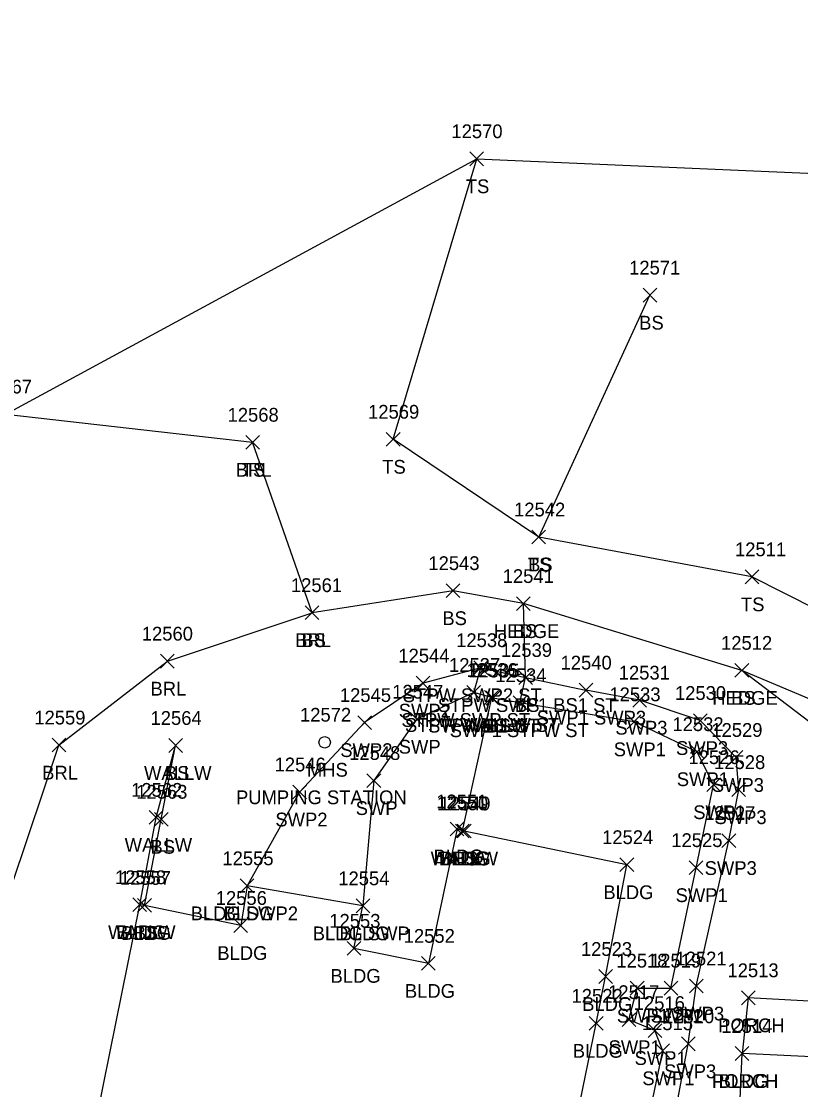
# Model space of a CAD drawing. Extents: x 1482574 to 1485769, y 580696 to 595649.
# Drawn here: x 1482734.1 to 1482847.5, y 584017.2 to 584172.5 of the extents above; entities that cross this region are included whole.
import ezdxf

# ---------------------------------------------------------------- set-up
doc = ezdxf.new("R2010")
doc.units = 0
for name, color, linetype in [('L_A', 7, 'Continuous'), ('L_I', 7, 'Continuous'), ('L_TIC', 7, 'Continuous'), ('LABL', 7, 'Continuous'), ('LAHR', 7, 'Continuous'), ('LBC', 7, 'Continuous'), ('LBF', 7, 'Continuous'), ('LELB', 7, 'Continuous'), ('LSOGP', 7, 'Continuous'), ('LW', 7, 'Continuous'), ('R_A', 7, 'Continuous'), ('R_I', 7, 'Continuous'), ('R_TIC', 7, 'Continuous'), ('RSW', 7, 'Continuous'), ('U_A', 7, 'Continuous'), ('U_C', 7, 'Continuous'), ('U_I', 7, 'Continuous'), ('USMH', 7, 'Continuous')]:
    doc.layers.add(name, color=color, linetype=linetype)

msp = doc.modelspace()

# ---------------------------------------------------------------- linework, layer by layer
at = {"layer": 'L_TIC'}
for points in [[(1482799.36, 584151.56), (1482801.36, 584153.56)], [(1482801.36, 584151.56), (1482799.36, 584153.56)], [(1482824.54, 584131.73), (1482826.54, 584133.73)], [(1482826.54, 584131.73), (1482824.54, 584133.73)], [(1482766.77, 584110.34), (1482768.77, 584112.34)], [(1482768.77, 584110.34), (1482766.77, 584112.34)], [(1482766.77, 584110.34), (1482768.77, 584112.34)], [(1482768.77, 584110.34), (1482766.77, 584112.34)], [(1482787.21, 584110.78), (1482789.21, 584112.78)], [(1482789.21, 584110.78), (1482787.21, 584112.78)], [(1482808.38, 584096.57), (1482810.38, 584098.57)], [(1482810.38, 584096.57), (1482808.38, 584098.57)], [(1482808.38, 584096.57), (1482810.38, 584098.57)], [(1482810.38, 584096.57), (1482808.38, 584098.57)], [(1482839.37, 584090.78), (1482841.37, 584092.78)], [(1482841.37, 584090.78), (1482839.37, 584092.78)], [(1482795.92, 584088.77), (1482797.92, 584090.77)], [(1482797.92, 584088.77), (1482795.92, 584090.77)], [(1482806.15, 584086.89), (1482808.15, 584088.89)], [(1482808.15, 584086.89), (1482806.15, 584088.89)], [(1482806.15, 584086.89), (1482808.15, 584088.89)], [(1482808.15, 584086.89), (1482806.15, 584088.89)], [(1482775.41, 584085.57), (1482777.41, 584087.57)], [(1482777.41, 584085.57), (1482775.41, 584087.57)], [(1482775.41, 584085.57), (1482777.41, 584087.57)], [(1482777.41, 584085.57), (1482775.41, 584087.57)], [(1482754.38, 584078.52), (1482756.38, 584080.52)], [(1482756.38, 584078.52), (1482754.38, 584080.52)], [(1482799.96, 584077.57), (1482801.96, 584079.57)], [(1482801.96, 584077.57), (1482799.96, 584079.57)], [(1482837.91, 584077.18), (1482839.91, 584079.18)], [(1482839.91, 584077.18), (1482837.91, 584079.18)], [(1482837.91, 584077.18), (1482839.91, 584079.18)], [(1482839.91, 584077.18), (1482837.91, 584079.18)], [(1482806.47, 584076.14), (1482808.47, 584078.14)], [(1482808.47, 584076.14), (1482806.47, 584078.14)], [(1482806.47, 584076.14), (1482808.47, 584078.14)], [(1482808.47, 584076.14), (1482806.47, 584078.14)], [(1482798.92, 584073.97), (1482800.92, 584075.97)], [(1482800.92, 584073.97), (1482798.92, 584075.97)], [(1482801.51, 584073.24), (1482803.51, 584075.24)], [(1482803.51, 584073.24), (1482801.51, 584075.24)], [(1482801.51, 584073.24), (1482803.51, 584075.24)], [(1482803.51, 584073.24), (1482801.51, 584075.24)], [(1482801.72, 584073.15), (1482803.72, 584075.15)], [(1482803.72, 584073.15), (1482801.72, 584075.15)], [(1482801.72, 584073.15), (1482803.72, 584075.15)], [(1482803.72, 584073.15), (1482801.72, 584075.15)], [(1482805.65, 584072.48), (1482807.65, 584074.48)], [(1482807.65, 584072.48), (1482805.65, 584074.48)], [(1482738.62, 584066.32), (1482740.62, 584068.32)], [(1482740.62, 584066.32), (1482738.62, 584068.32)], [(1482755.57, 584066.26), (1482757.57, 584068.26)], [(1482757.57, 584066.26), (1482755.57, 584068.26)], [(1482755.57, 584066.26), (1482757.57, 584068.26)], [(1482757.57, 584066.26), (1482755.57, 584068.26)], [(1482752.75, 584055.81), (1482754.75, 584057.81)], [(1482754.75, 584055.81), (1482752.75, 584057.81)], [(1482753.49, 584055.53), (1482755.49, 584057.53)], [(1482755.49, 584055.53), (1482753.49, 584057.53)], [(1482796.5, 584054.13), (1482798.5, 584056.13)], [(1482798.5, 584054.13), (1482796.5, 584056.13)], [(1482797.25, 584053.85), (1482799.25, 584055.85)], [(1482799.25, 584053.85), (1482797.25, 584055.85)], [(1482797.25, 584053.85), (1482799.25, 584055.85)], [(1482799.25, 584053.85), (1482797.25, 584055.85)], [(1482797.53, 584053.83), (1482799.53, 584055.83)], [(1482799.53, 584053.83), (1482797.53, 584055.83)], [(1482797.53, 584053.83), (1482799.53, 584055.83)], [(1482799.53, 584053.83), (1482797.53, 584055.83)], [(1482821.18, 584048.93), (1482823.18, 584050.93)], [(1482823.18, 584048.93), (1482821.18, 584050.93)], [(1482765.97, 584045.86), (1482767.97, 584047.86)], [(1482767.97, 584045.86), (1482765.97, 584047.86)], [(1482750.35, 584043.11), (1482752.35, 584045.11)], [(1482752.35, 584043.11), (1482750.35, 584045.11)], [(1482750.35, 584043.11), (1482752.35, 584045.11)], [(1482752.35, 584043.11), (1482750.35, 584045.11)], [(1482750.35, 584043.11), (1482752.35, 584045.11)], [(1482752.35, 584043.11), (1482750.35, 584045.11)], [(1482751.05, 584043.01), (1482753.05, 584045.01)], [(1482753.05, 584043.01), (1482751.05, 584045.01)], [(1482751.05, 584043.01), (1482753.05, 584045.01)], [(1482753.05, 584043.01), (1482751.05, 584045.01)], [(1482782.82, 584042.95), (1482784.82, 584044.95)], [(1482784.82, 584042.95), (1482782.82, 584044.95)], [(1482765.05, 584040.09), (1482767.05, 584042.09)], [(1482767.05, 584040.09), (1482765.05, 584042.09)], [(1482781.51, 584036.77), (1482783.51, 584038.77)], [(1482783.51, 584036.77), (1482781.51, 584038.77)], [(1482792.33, 584034.58), (1482794.33, 584036.58)], [(1482794.33, 584034.58), (1482792.33, 584036.58)], [(1482818.1, 584032.68), (1482820.1, 584034.68)], [(1482820.1, 584032.68), (1482818.1, 584034.68)], [(1482838.85, 584029.58), (1482840.85, 584031.58)], [(1482840.85, 584029.58), (1482838.85, 584031.58)], [(1482816.73, 584025.87), (1482818.73, 584027.87)], [(1482818.73, 584025.87), (1482816.73, 584027.87)], [(1482837.94, 584021.48), (1482839.94, 584023.48)], [(1482839.94, 584021.48), (1482837.94, 584023.48)], [(1482837.94, 584021.48), (1482839.94, 584023.48)], [(1482839.94, 584021.48), (1482837.94, 584023.48)], [(1482837.94, 584021.48), (1482839.94, 584023.48)], [(1482839.94, 584021.48), (1482837.94, 584023.48)]]:
    msp.add_lwpolyline(points, dxfattribs=at)
at = {"layer": 'LABL'}
msp.add_lwpolyline([(1482753.56, 583847.65), (1482763.33, 583886.22), (1482745, 583925.11), (1482720.19, 583937.3), (1482697, 583950.74), (1482684.74, 583977.37), (1482717.6, 583981.37), (1482723.72, 584020.13), (1482739.62, 584067.32), (1482755.38, 584079.52), (1482776.41, 584086.57), (1482767.77, 584111.34)], dxfattribs=at)
at = {"layer": 'LAHR'}
msp.add_lwpolyline([(1482928.6, 584026.89), (1482913.75, 584044.71), (1482891.08, 584056.23), (1482855.52, 584065.51), (1482838.91, 584078.18), (1482807.15, 584087.89)], dxfattribs=at)
at = {"layer": 'LBC'}
for points in [[(1482808.73, 583982.89), (1482817.73, 584026.87), (1482819.1, 584033.68), (1482822.18, 584049.93), (1482798.53, 584054.83), (1482798.25, 584054.85), (1482797.5, 584055.13), (1482793.33, 584035.58), (1482782.51, 584037.77), (1482783.82, 584043.95), (1482766.97, 584046.86), (1482766.05, 584041.09), (1482752.05, 584044.01), (1482751.35, 584044.11)], [(1482741.74, 583996.43), (1482751.35, 584044.11)], [(1482837.55, 583990.35), (1482890.4, 583987.41), (1482892.38, 583987.48), (1482894.08, 584019.69), (1482891.62, 584019.98), (1482838.94, 584022.48)], [(1482837.55, 583990.35), (1482838.94, 584022.48)]]:
    msp.add_lwpolyline(points, dxfattribs=at)
at = {"layer": 'LBF'}
for points in [[(1482806.65, 584073.48), (1482802.72, 584074.15), (1482802.51, 584074.24), (1482799.92, 584074.97), (1482800.96, 584078.57), (1482807.47, 584077.14)], [(1482891.62, 584019.98), (1482892.34, 584027.71), (1482839.85, 584030.58), (1482838.94, 584022.48)]]:
    msp.add_lwpolyline(points, dxfattribs=at)
at = {"layer": 'LELB'}
for points in [[(1482942.03, 583859.02), (1482934.27, 583897.38), (1482938.31, 583954.48), (1482940.22, 584002.41), (1482937.55, 584028.27), (1482922.03, 584053.68), (1482893.04, 584067.31), (1482864.04, 584079.81), (1482840.37, 584091.78), (1482809.38, 584097.57), (1482788.21, 584111.78), (1482800.36, 584152.56)], [(1482809.38, 584097.57), (1482825.54, 584132.73)], [(1482704.84, 584111.05), (1482731.9, 584115.44), (1482767.77, 584111.34)], [(1482807.47, 584077.14), (1482807.15, 584087.89), (1482796.92, 584089.77), (1482776.41, 584086.57)], [(1482935.97, 583858.21), (1482928.85, 583898.87), (1482930.75, 583906.84), (1482932.59, 583955.77), (1482933.96, 584002.2), (1482933.04, 584027.34), (1482916.05, 584047.49), (1482891.95, 584059.4), (1482858.9, 584069.72), (1482838.91, 584078.18)], [(1482752.05, 584044.01), (1482754.49, 584056.53), (1482756.57, 584067.26)]]:
    msp.add_lwpolyline(points, dxfattribs=at)
at = {"layer": 'LSOGP'}
msp.add_lwpolyline([(1482624.36, 583828.83), (1482673.16, 583862.27), (1482696.29, 583884.43), (1482694.49, 583917.75), (1482678.31, 583954.25), (1482684.74, 583977.37), (1482695.23, 584028.52), (1482699.57, 584054.68), (1482704.09, 584083.33), (1482704.84, 584111.05), (1482731.9, 584115.44), (1482800.36, 584152.56), (1482886.43, 584148.82), (1482927.74, 584160.45), (1482970.01, 584172.54)], dxfattribs=at)
at = {"layer": 'LW'}
for points in [[(1482802.51, 584074.24), (1482798.25, 584054.85)], [(1482751.35, 584044.11), (1482753.75, 584056.81), (1482756.57, 584067.26)]]:
    msp.add_lwpolyline(points, dxfattribs=at)
at = {"layer": 'R_TIC'}
for points in [[(1482799.96, 584077.57), (1482801.96, 584079.57)], [(1482801.96, 584077.57), (1482799.96, 584079.57)], [(1482791.55, 584075.33), (1482793.55, 584077.33)], [(1482793.55, 584075.33), (1482791.55, 584077.33)], [(1482806.47, 584076.14), (1482808.47, 584078.14)], [(1482808.47, 584076.14), (1482806.47, 584078.14)], [(1482798.92, 584073.97), (1482800.92, 584075.97)], [(1482800.92, 584073.97), (1482798.92, 584075.97)], [(1482815.23, 584074.31), (1482817.23, 584076.31)], [(1482817.23, 584074.31), (1482815.23, 584076.31)], [(1482815.23, 584074.31), (1482817.23, 584076.31)], [(1482817.23, 584074.31), (1482815.23, 584076.31)], [(1482805.65, 584072.48), (1482807.65, 584074.48)], [(1482807.65, 584072.48), (1482805.65, 584074.48)], [(1482823.04, 584072.85), (1482825.04, 584074.85)], [(1482825.04, 584072.85), (1482823.04, 584074.85)], [(1482783.05, 584069.59), (1482785.05, 584071.59)], [(1482785.05, 584069.59), (1482783.05, 584071.59)], [(1482790.66, 584070.08), (1482792.66, 584072.08)], [(1482792.66, 584070.08), (1482790.66, 584072.08)], [(1482822.24, 584069.7), (1482824.24, 584071.7)], [(1482824.24, 584069.7), (1482822.24, 584071.7)], [(1482831.86, 584069.89), (1482833.86, 584071.89)], [(1482833.86, 584069.89), (1482831.86, 584071.89)], [(1482831.41, 584065.36), (1482833.41, 584067.36)], [(1482833.41, 584065.36), (1482831.41, 584067.36)], [(1482837.07, 584064.52), (1482839.07, 584066.52)], [(1482839.07, 584064.52), (1482837.07, 584066.52)], [(1482784.4, 584061.16), (1482786.4, 584063.16)], [(1482786.4, 584061.16), (1482784.4, 584063.16)], [(1482833.8, 584060.56), (1482835.8, 584062.56)], [(1482835.8, 584060.56), (1482833.8, 584062.56)], [(1482837.46, 584059.84), (1482839.46, 584061.84)], [(1482839.46, 584059.84), (1482837.46, 584061.84)], [(1482773.61, 584059.5), (1482775.61, 584061.5)], [(1482775.61, 584059.5), (1482773.61, 584061.5)], [(1482836.02, 584052.44), (1482838.02, 584054.44)], [(1482838.02, 584052.44), (1482836.02, 584054.44)], [(1482831.25, 584048.5), (1482833.25, 584050.5)], [(1482833.25, 584048.5), (1482831.25, 584050.5)], [(1482765.97, 584045.86), (1482767.97, 584047.86)], [(1482767.97, 584045.86), (1482765.97, 584047.86)], [(1482782.82, 584042.95), (1482784.82, 584044.95)], [(1482784.82, 584042.95), (1482782.82, 584044.95)], [(1482822.69, 584030.98), (1482824.69, 584032.98)], [(1482824.69, 584030.98), (1482822.69, 584032.98)], [(1482827.59, 584030.98), (1482829.59, 584032.98)], [(1482829.59, 584030.98), (1482827.59, 584032.98)], [(1482831.28, 584031.29), (1482833.28, 584033.29)], [(1482833.28, 584031.29), (1482831.28, 584033.29)], [(1482821.49, 584026.4), (1482823.49, 584028.4)], [(1482823.49, 584026.4), (1482821.49, 584028.4)], [(1482825.27, 584024.82), (1482827.27, 584026.82)], [(1482827.27, 584024.82), (1482825.27, 584026.82)], [(1482830.12, 584022.89), (1482832.12, 584024.89)], [(1482832.12, 584022.89), (1482830.12, 584024.89)], [(1482826.4, 584021.88), (1482828.4, 584023.88)], [(1482828.4, 584021.88), (1482826.4, 584023.88)]]:
    msp.add_lwpolyline(points, dxfattribs=at)
at = {"layer": 'RSW'}
for points in [[(1482800.96, 584078.57), (1482792.55, 584076.33), (1482784.05, 584070.59), (1482774.61, 584060.5), (1482766.97, 584046.86)], [(1482823.31, 583939.7), (1482822.04, 583959.32), (1482819.45, 583984.29), (1482821.45, 583994.26), (1482827.4, 584022.88), (1482826.27, 584025.82), (1482822.49, 584027.4), (1482823.69, 584031.98), (1482828.59, 584031.98), (1482832.25, 584049.5), (1482834.8, 584061.56), (1482832.41, 584066.36), (1482823.24, 584070.7), (1482806.65, 584073.48), (1482807.47, 584077.14), (1482816.23, 584075.31)], [(1482799.92, 584074.97), (1482791.66, 584071.08), (1482785.4, 584062.16), (1482783.82, 584043.95)], [(1482827.72, 583940.25), (1482825.42, 583959.17), (1482823.58, 583984.19), (1482827.5, 583986.02), (1482836.38, 583984.37), (1482836.5, 583988.78), (1482826.87, 583989.35), (1482825.22, 583992.27), (1482831.12, 584023.89), (1482832.28, 584032.29), (1482837.02, 584053.44), (1482838.46, 584060.84), (1482838.07, 584065.52), (1482832.86, 584070.89), (1482824.04, 584073.85), (1482816.23, 584075.31)]]:
    msp.add_lwpolyline(points, dxfattribs=at)
at = {"layer": 'USMH'}
for p, q in [((1482778.25, 584067.73), (1482778.25, 584067.73)), ((1482779.08, 584067.73), (1482779.08, 584067.73))]:
    msp.add_line(p, q, dxfattribs=at)
msp.add_circle((1482778.25, 584067.73), 0.833, dxfattribs=at)

# ---------------------------------------------------------------- texts
at = {"layer": 'L_A'}
for s, p in [('TS', (1482798.77, 584147.56)), ('BS', (1482823.98, 584127.73)), ('BRL', (1482765.31, 584106.34)), ('TS', (1482766.18, 584106.34)), ('TS', (1482786.62, 584106.78)), ('TS', (1482807.79, 584092.57)), ('BS', (1482807.82, 584092.57)), ('TS', (1482838.78, 584086.78)), ('BS', (1482795.36, 584084.77)), ('HEDGE', (1482802.85, 584082.89)), ('BS', (1482805.59, 584082.89)), ('BRL', (1482773.96, 584081.57)), ('BS', (1482774.86, 584081.57)), ('BRL', (1482752.92, 584074.52)), ('STPW SWP2 ST', (1482789.6, 584073.57)), ('STPW SWP1 BS1 ST', (1482794.69, 584072.14)), ('BS', (1482805.91, 584072.14)), ('HEDGE', (1482834.61, 584073.18)), ('BS', (1482837.35, 584073.18)), ('STPW SWP ST', (1482789.41, 584069.97)), ('STPW WALLW ST', (1482789.92, 584069.24)), ('STPW BS ST', (1482793.28, 584069.15)), ('WALLW', (1482797.93, 584069.24)), ('BS', (1482801.16, 584069.15)), ('SWP1 STPW ST', (1482796.43, 584068.48)), ('BRL', (1482737.17, 584062.32)), ('WALLW', (1482751.99, 584062.26)), ('BS', (1482755.01, 584062.26)), ('WALLW', (1482749.17, 584051.81)), ('BS', (1482752.93, 584051.53)), ('WALLW', (1482793.66, 584049.85)), ('BLDG', (1482794.09, 584050.13)), ('BLDG', (1482794.84, 584049.85)), ('BLDG', (1482795.12, 584049.83)), ('BS', (1482796.97, 584049.83)), ('BLDG', (1482818.77, 584044.93)), ('BLDG', (1482763.56, 584041.86)), ('WALLW', (1482746.76, 584039.11)), ('BLDG', (1482747.94, 584039.11)), ('BLDG', (1482747.94, 584039.11)), ('BLDG', (1482748.64, 584039.01)), ('BS', (1482750.49, 584039.01)), ('BLDG', (1482780.41, 584038.95)), ('BLDG', (1482762.64, 584036.09)), ('BLDG', (1482779.1, 584032.77)), ('BLDG', (1482789.92, 584030.58)), ('BLDG', (1482815.69, 584028.68)), ('PORCH', (1482835.47, 584025.58)), ('BLDG', (1482814.32, 584021.87)), ('PORCH', (1482834.56, 584017.48)), ('BLDG', (1482835.53, 584017.48)), ('BLDG', (1482835.53, 584017.48))]:
    msp.add_text(s, height=2, dxfattribs=at).set_placement(p)
at = {"layer": 'L_I'}
for s, p in [('12570', (1482796.68, 584155.56)), ('12571', (1482822.52, 584135.73)), ('12567', (1482728.26, 584118.44)), ('12568', (1482764.13, 584114.34)), ('12568', (1482764.13, 584114.34)), ('12569', (1482784.56, 584114.78)), ('12542', (1482805.79, 584100.57)), ('12542', (1482805.79, 584100.57)), ('12511', (1482837.91, 584094.78)), ('12543', (1482793.33, 584092.77)), ('12541', (1482804.13, 584090.89)), ('12541', (1482804.13, 584090.89)), ('12561', (1482773.34, 584089.57)), ('12561', (1482773.34, 584089.57)), ('12560', (1482751.66, 584082.52)), ('12538', (1482797.37, 584081.57)), ('12539', (1482803.87, 584080.14)), ('12539', (1482803.87, 584080.14)), ('12512', (1482835.88, 584081.18)), ('12512', (1482835.88, 584081.18)), ('12537', (1482796.33, 584077.97)), ('12536', (1482798.87, 584077.24)), ('12536', (1482798.87, 584077.24)), ('12535', (1482799.13, 584077.15)), ('12535', (1482799.13, 584077.15)), ('12534', (1482803.06, 584076.48)), ('12559', (1482736.03, 584070.32)), ('12564', (1482752.93, 584070.26)), ('12564', (1482752.93, 584070.26)), ('12562', (1482750.11, 584059.81)), ('12563', (1482750.85, 584059.53)), ('12551', (1482794.47, 584058.13)), ('12550', (1482794.57, 584057.85)), ('12550', (1482794.57, 584057.85)), ('12549', (1482794.93, 584057.83)), ('12549', (1482794.93, 584057.83)), ('12524', (1482818.59, 584052.93)), ('12555', (1482763.38, 584049.86)), ('12558', (1482747.76, 584047.11)), ('12558', (1482747.76, 584047.11)), ('12558', (1482747.76, 584047.11)), ('12557', (1482748.46, 584047.01)), ('12557', (1482748.46, 584047.01)), ('12554', (1482780.23, 584046.95)), ('12556', (1482762.41, 584044.09)), ('12553', (1482778.92, 584040.77)), ('12552', (1482789.74, 584038.58)), ('12523', (1482815.51, 584036.68)), ('12513', (1482836.82, 584033.58)), ('12522', (1482814.14, 584029.87)), ('12514', (1482835.91, 584025.48)), ('12514', (1482835.91, 584025.48)), ('12514', (1482835.91, 584025.48))]:
    msp.add_text(s, height=2, dxfattribs=at).set_placement(p)
at = {"layer": 'R_A'}
for s, p in [('STPW SWP2 ST', (1482789.6, 584073.57)), ('STPW SWP1 BS1 ST', (1482794.69, 584072.14)), ('SWP2', (1482789.02, 584071.33)), ('STPW SWP ST', (1482789.41, 584069.97)), ('SWP1 SWP3', (1482809.08, 584070.31)), ('SWP1 SWP3', (1482809.08, 584070.31)), ('SWP3', (1482820.51, 584068.85)), ('SWP1 STPW ST', (1482796.43, 584068.48)), ('SWP', (1482789.02, 584066.08)), ('SWP3', (1482829.33, 584065.89)), ('SWP2', (1482780.52, 584065.59)), ('SWP1', (1482820.28, 584065.7)), ('SWP1', (1482829.45, 584061.36)), ('SWP3', (1482834.54, 584060.52)), ('SWP', (1482782.76, 584057.16)), ('SWP1', (1482831.84, 584056.56)), ('SWP2', (1482771.08, 584055.5)), ('SWP3', (1482834.93, 584055.84)), ('SWP3', (1482833.5, 584048.44)), ('SWP1', (1482829.28, 584044.5)), ('BLDG SWP2', (1482758.77, 584041.86)), ('BLDG SWP', (1482776.51, 584038.95)), ('SWP1', (1482820.73, 584026.98)), ('SWP1', (1482825.62, 584026.98)), ('SWP3', (1482828.75, 584027.29)), ('SWP1', (1482819.53, 584022.4)), ('SWP1', (1482823.31, 584020.82)), ('SWP1', (1482824.44, 584017.88)), ('SWP3', (1482827.6, 584018.89))]:
    msp.add_text(s, height=2, dxfattribs=at).set_placement(p)
at = {"layer": 'R_I'}
for s, p in [('12538', (1482797.37, 584081.57)), ('12539', (1482803.87, 584080.14)), ('12544', (1482788.96, 584079.33)), ('12540', (1482812.55, 584078.31)), ('12540', (1482812.55, 584078.31)), ('12537', (1482796.33, 584077.97)), ('12531', (1482821.01, 584076.85)), ('12534', (1482803.06, 584076.48)), ('12545', (1482780.46, 584073.59)), ('12547', (1482788.07, 584074.08)), ('12533', (1482819.65, 584073.7)), ('12530', (1482829.18, 584073.89)), ('12532', (1482828.82, 584069.36)), ('12529', (1482834.47, 584068.52)), ('12548', (1482781.81, 584065.16)), ('12526', (1482831.15, 584064.56)), ('12546', (1482770.97, 584063.5)), ('12528', (1482834.87, 584063.84)), ('12527', (1482833.43, 584056.44)), ('12525', (1482828.65, 584052.5)), ('12555', (1482763.38, 584049.86)), ('12554', (1482780.23, 584046.95)), ('12518', (1482820.66, 584034.98)), ('12519', (1482825.55, 584034.98)), ('12521', (1482829.25, 584035.29)), ('12517', (1482819.47, 584030.4)), ('12516', (1482823.19, 584028.82)), ('12515', (1482824.37, 584025.88)), ('12520', (1482827.45, 584026.89))]:
    msp.add_text(s, height=2, dxfattribs=at).set_placement(p)
at = {"layer": 'U_A'}
msp.add_text('MHS', height=2, dxfattribs=at).set_placement((1482775.67, 584062.73))
at = {"layer": 'U_C'}
msp.add_text('PUMPING STATION', height=2, dxfattribs=at).set_placement((1482765.36, 584058.73))
at = {"layer": 'U_I'}
msp.add_text('12572', height=2, dxfattribs=at).set_placement((1482774.66, 584070.73))

doc.saveas('drawing.dxf')
